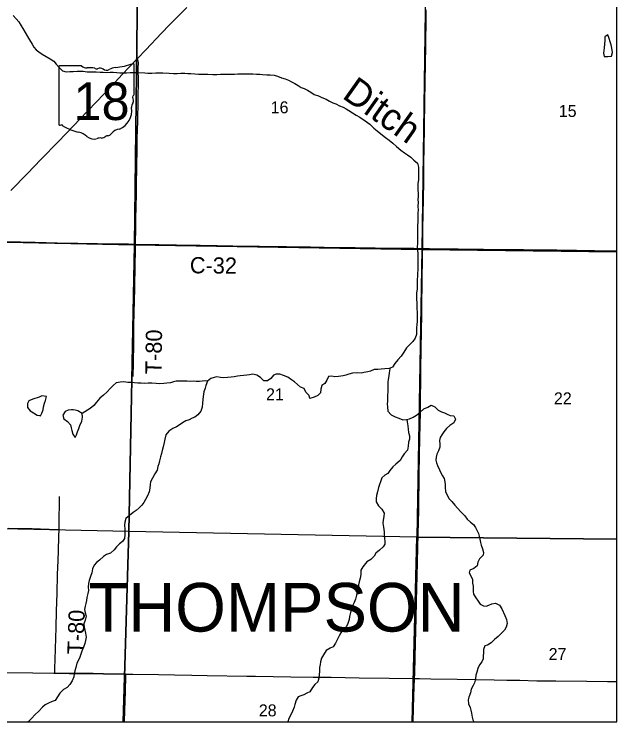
# Model space of a CAD drawing. Extents: x -8.5 to 18.7, y -20.3 to 7.
# Drawn here: x 14.521 to 18.741, y -20.262 to -15.303 of the extents above; entities that cross this region are included whole.
import ezdxf

# ---------------------------------------------------------------- set-up
doc = ezdxf.new("R2010")
doc.units = 0
for name, color, linetype in [('GM_X_Corporation', 7, 'Continuous'), ('GM_X_County_Road', 7, 'Continuous'), ('GM_X_County_Road_Text', 7, 'Continuous'), ('GM_X_Minor_Lake', 7, 'Continuous'), ('GM_X_Minor_River', 7, 'Continuous'), ('GM_X_Minor_River_Text', 7, 'Continuous'), ('GM_X_Section', 7, 'Continuous'), ('GM_X_Section_Text', 7, 'Continuous'), ('GM_X_State_Location', 7, 'Continuous'), ('GM_X_State_Route', 7, 'Continuous'), ('GM_X_State_Shield', 7, 'Continuous'), ('GM_X_Township_Road', 7, 'Continuous'), ('GM_X_Township_Road_Text', 7, 'Continuous'), ('GM_X_Township_Text', 7, 'Continuous'), ('GM_X_Unincorporated_Text', 7, 'Continuous'), ('SH_Cut_Line', 7, 'Continuous')]:
    doc.layers.add(name, color=color, linetype=linetype)

msp = doc.modelspace()

# ---------------------------------------------------------------- linework, layer by layer
at = {"layer": 'GM_X_Corporation'}
msp.add_lwpolyline([(11.2623, -20.262), (18.7413, -20.262), (18.7413, -10.9039)], dxfattribs=at)
at = {"layer": 'GM_X_County_Road'}
for points in [[(14.1487, -16.8895), (14.1591, -16.8897), (14.2125, -16.8915), (14.2784, -16.893), (14.3268, -16.8937), (14.4449, -16.8962), (14.5643, -16.8985), (14.6686, -16.9014), (14.8228, -16.9045), (14.9657, -16.9071), (15.2454, -16.9126), (15.3212, -16.9133), (15.3705, -16.9142)], [(15.3705, -16.9142), (15.5338, -16.9174), (15.6581, -16.9197), (15.8222, -16.9221), (15.9415, -16.9245), (16.0509, -16.9259), (16.2399, -16.9289), (16.3356, -16.9307), (16.3828, -16.9311), (16.4288, -16.9315), (16.4997, -16.9331), (16.5966, -16.934), (16.6924, -16.9355), (16.8079, -16.9372), (16.9099, -16.9383), (17.0491, -16.9399), (17.1635, -16.9417), (17.294, -16.9431), (17.3188, -16.9431), (17.382, -16.9445)], [(17.382, -16.9445), (17.4294, -16.9456), (17.6296, -16.9473), (17.7278, -16.9486), (17.8086, -16.9494), (17.9752, -16.9513), (18.051, -16.9524), (18.087, -16.953), (18.1541, -16.9533), (18.2187, -16.9541), (18.3219, -16.9549), (18.4587, -16.9567), (18.7122, -16.9608), (18.7413, -16.9611)], [(13.3025, -19.8984), (13.3396, -19.8991), (13.4602, -19.9008), (13.5161, -19.9015), (13.5919, -19.9033), (13.8717, -19.9075), (14.0382, -19.9103), (14.124, -19.9116), (14.267, -19.9132), (14.4261, -19.9156), (14.6524, -19.9183), (14.7978, -19.9203), (14.8047, -19.9204)], [(14.8047, -19.9204), (14.906, -19.9221), (14.9744, -19.9227), (15.0738, -19.9242), (15.1472, -19.9246), (15.3033, -19.9272)], [(15.3033, -19.9272), (15.3523, -19.928), (15.5313, -19.931), (15.6432, -19.9329), (15.765, -19.9352), (15.8731, -19.9367), (16.1491, -19.942), (16.2112, -19.9426), (16.4587, -19.9459), (16.6153, -19.9486), (16.7409, -19.9496), (16.9361, -19.9528), (17.1461, -19.9564), (17.3249, -19.9582)], [(17.3249, -19.9582), (17.3585, -19.9585), (17.4395, -19.9602), (17.6222, -19.9634), (17.7552, -19.9655), (17.8833, -19.9681), (17.9715, -19.9697), (18.061, -19.9709), (18.1803, -19.9736), (18.2487, -19.9745), (18.3133, -19.9753), (18.5321, -19.9778), (18.6751, -19.9788), (18.7413, -19.9795)]]:
    msp.add_lwpolyline(points, dxfattribs=at)
at = {"layer": 'GM_X_Minor_Lake'}
for points in [[(18.6631, -15.4571), (18.6579, -15.4602), (18.6563, -15.4875), (18.6547, -15.5133), (18.6523, -15.5383), (18.65, -15.5573), (18.6484, -15.577), (18.6521, -15.6006)], [(18.6521, -15.6006), (18.6771, -15.6007), (18.7036, -15.5978), (18.7105, -15.572), (18.7068, -15.5424), (18.7024, -15.5173), (18.6957, -15.4968), (18.6867, -15.4733), (18.6777, -15.4482), (18.6631, -15.4571)], [(14.7467, -17.9826), (14.7149, -17.9779), (14.696, -17.9862), (14.6504, -18.0011), (14.6224, -18.0124), (14.6132, -18.032), (14.6146, -18.0601), (14.6327, -18.0837), (14.6569, -18.0967), (14.6811, -18.1135), (14.697, -18.1165)], [(14.697, -18.1165), (14.706, -18.1182), (14.7137, -18.0985), (14.7236, -18.075), (14.7252, -18.0553), (14.7337, -18.0296), (14.7406, -18.0091), (14.7467, -17.9826)], [(14.9329, -18.0762), (14.9213, -18.0745), (14.8994, -18.0789), (14.8774, -18.0879), (14.8606, -18.1136), (14.8696, -18.1395), (14.8953, -18.1563), (14.9141, -18.1799), (14.9193, -18.2027), (14.9253, -18.2216), (14.9313, -18.2452), (14.9486, -18.2703)], [(14.9486, -18.2703), (14.9578, -18.2499), (14.9631, -18.2302), (14.9738, -18.2075), (14.9815, -18.1863), (14.9945, -18.156), (14.9999, -18.1279), (14.9962, -18.1021), (14.9675, -18.083), (14.9471, -18.0784), (14.9329, -18.0762)]]:
    msp.add_lwpolyline(points, dxfattribs=at)
at = {"layer": 'GM_X_Minor_River'}
for points in [[(14.5126, -15.3125), (14.5345, -15.3361), (14.5533, -15.3567), (14.5699, -15.3841), (14.5819, -15.4039), (14.5977, -15.4312), (14.6143, -15.4586), (14.6286, -15.4837), (14.6459, -15.5127), (14.6587, -15.5332), (14.6745, -15.5522), (14.6941, -15.566), (14.716, -15.5835), (14.7448, -15.5989), (14.7735, -15.6157), (14.7984, -15.6332), (14.8158, -15.6538), (14.8376, -15.6782), (14.8588, -15.7011), (14.8837, -15.7065), (14.9103, -15.7059), (14.9345, -15.7052)], [(14.9345, -15.7052), (14.961, -15.7023), (14.9822, -15.7024), (15.0034, -15.7033), (15.0322, -15.7064), (15.0527, -15.7065), (15.0754, -15.7081), (15.0958, -15.7082), (15.1239, -15.7091), (15.1443, -15.71), (15.1663, -15.7109), (15.1936, -15.7095), (15.2132, -15.7096), (15.2405, -15.7127), (15.2602, -15.7136), (15.2875, -15.7152), (15.3072, -15.7145), (15.3329, -15.7124), (15.3587, -15.7118), (15.3913, -15.7119), (15.4352, -15.7152), (15.4571, -15.716), (15.4844, -15.7161), (15.5125, -15.7148), (15.5367, -15.7134), (15.5617, -15.7135), (15.6064, -15.716), (15.6359, -15.7184), (15.6624, -15.7185), (15.6874, -15.7171), (15.717, -15.7165), (15.7374, -15.7181), (15.7571, -15.7189), (15.7866, -15.7214), (15.8116, -15.723), (15.8518, -15.7232), (15.876, -15.7241), (15.9109, -15.725), (15.9404, -15.7259), (15.9654, -15.7237), (15.9866, -15.7231), (16.0162, -15.7224), (16.0381, -15.7241), (16.0631, -15.7234), (16.0881, -15.722), (16.1124, -15.7221), (16.1397, -15.7207), (16.1631, -15.7209), (16.1927, -15.7218), (16.2184, -15.7226), (16.2404, -15.7243), (16.2601, -15.7251), (16.2904, -15.7283), (16.3139, -15.7284), (16.3404, -15.7316), (16.3638, -15.7385), (16.3926, -15.7485), (16.4175, -15.7562), (16.441, -15.7654), (16.4674, -15.7792), (16.4871, -15.7891), (16.509, -15.8029), (16.5309, -15.8159), (16.5521, -15.8244), (16.574, -15.8366), (16.5974, -15.8504), (16.6216, -15.8649), (16.6511, -15.8764), (16.6761, -15.8879), (16.7056, -15.8994), (16.7283, -15.9124), (16.7525, -15.9239), (16.7729, -15.9316), (16.8001, -15.9462), (16.8251, -15.9554), (16.8447, -15.9669), (16.8651, -15.9783), (16.89, -15.9944), (16.915, -16.0112), (16.9414, -16.025), (16.9792, -16.0502), (17.0109, -16.0739), (17.0396, -16.1013), (17.0623, -16.1211), (17.0879, -16.1425), (17.1204, -16.1662), (17.1468, -16.186), (17.1733, -16.2074), (17.1989, -16.2303), (17.2276, -16.2562), (17.2533, -16.2745), (17.276, -16.2883), (17.2979, -16.3051), (17.3205, -16.3264), (17.3462, -16.3471), (17.3529, -16.3744), (17.3528, -16.3964), (17.352, -16.4192), (17.3518, -16.4624), (17.3479, -16.4912), (17.3478, -16.5109)], [(17.3478, -16.5109), (17.3485, -16.5367), (17.3499, -16.558), (17.3491, -16.5807), (17.3482, -16.602), (17.3489, -16.6217), (17.3488, -16.649), (17.3495, -16.6756), (17.3486, -16.6953), (17.3484, -16.7552), (17.346, -16.7856), (17.3444, -16.8083), (17.3442, -16.8546), (17.3456, -16.885), (17.3463, -16.907), (17.3431, -16.9365), (17.3453, -16.9578), (17.3475, -16.9828), (17.3481, -17.0056), (17.3479, -17.0557), (17.3486, -17.0747), (17.347, -17.0951), (17.3447, -17.1186), (17.3461, -17.1399), (17.343, -17.1634), (17.3427, -17.2286), (17.3381, -17.2574), (17.338, -17.2832), (17.3386, -17.303), (17.3401, -17.3242), (17.3407, -17.3485), (17.3414, -17.3682), (17.3421, -17.3902), (17.3428, -17.41), (17.3434, -17.432), (17.3433, -17.457), (17.3417, -17.4775), (17.3394, -17.5002), (17.3393, -17.5298), (17.3377, -17.5488), (17.33, -17.5745), (17.3125, -17.5972), (17.2897, -17.6206), (17.2691, -17.6402), (17.2501, -17.6713), (17.231, -17.6992), (17.2074, -17.7257), (17.1869, -17.7499), (17.1693, -17.7771), (17.1473, -17.7861), (17.1155, -17.7882), (17.092, -17.7904), (17.0685, -17.7933), (17.042, -17.7939), (17.0162, -17.8052), (16.9973, -17.8089), (16.9692, -17.8148), (16.9503, -17.8185), (16.9245, -17.8169), (16.8912, -17.8183), (16.8646, -17.8257), (16.8434, -17.8324), (16.8237, -17.8369), (16.7926, -17.8428), (16.7661, -17.8442), (16.7464, -17.8388), (16.7222, -17.841), (16.7092, -17.8682), (16.697, -17.8917), (16.6757, -17.9052), (16.6688, -17.9318), (16.6671, -17.9575), (16.6466, -17.9749), (16.6223, -17.9877), (16.592, -17.9951), (16.5868, -17.9761), (16.5634, -17.951), (16.5506, -17.9251), (16.5257, -17.9159), (16.5038, -17.8976), (16.4841, -17.8801), (16.4637, -17.8648), (16.4381, -17.8457), (16.4078, -17.8357), (16.3813, -17.8249), (16.3556, -17.8248), (16.3366, -17.8331), (16.3191, -17.8565), (16.294, -17.8716), (16.2698, -17.8722), (16.2449, -17.8493), (16.2207, -17.8333), (16.1912, -17.8263), (16.1692, -17.8308), (16.1495, -17.833), (16.1268, -17.8351), (16.104, -17.8365), (16.0851, -17.8402), (16.0608, -17.8447), (16.0411, -17.8469)], [(17.1508, -17.7847), (17.1526, -17.7891), (17.1465, -17.8157), (17.1434, -17.8369), (17.1395, -17.8619), (17.1386, -17.8816), (17.1378, -17.9029), (17.1369, -17.9271), (17.1369, -17.9476), (17.136, -17.9757), (17.1343, -18.0151), (17.1335, -18.0364), (17.1341, -18.0553), (17.1378, -18.0842), (17.162, -18.1101), (17.1884, -18.1254), (17.2141, -18.1346), (17.2429, -18.1446), (17.2694, -18.144), (17.2884, -18.138), (17.3149, -18.1267), (17.3392, -18.1132), (17.3628, -18.0944), (17.3894, -18.0694), (17.4175, -18.0574), (17.4417, -18.0439), (17.4675, -18.0546), (17.4908, -18.0775), (17.5143, -18.089), (17.534, -18.0959), (17.5536, -18.1059), (17.5733, -18.1143), (17.6005, -18.1167), (17.6103, -18.141), (17.5988, -18.166), (17.5722, -18.1849), (17.5479, -18.2067), (17.5304, -18.2294), (17.5167, -18.2498), (17.5052, -18.2695), (17.4998, -18.29), (17.502, -18.3165), (17.5012, -18.3378), (17.4935, -18.362), (17.4798, -18.387), (17.4751, -18.4082), (17.4743, -18.4279), (17.478, -18.4469), (17.4855, -18.4659), (17.4998, -18.4955), (17.5088, -18.5168), (17.5193, -18.5374), (17.5313, -18.5571), (17.5366, -18.5807), (17.5387, -18.6012), (17.5387, -18.6201), (17.5408, -18.6482), (17.5521, -18.6733), (17.5679, -18.6984), (17.5852, -18.7182), (17.6071, -18.7433), (17.6252, -18.7639), (17.6493, -18.7898), (17.6757, -18.8195), (17.6923, -18.8408), (17.7172, -18.8637), (17.7376, -18.879), (17.7504, -18.9003), (17.7639, -18.9231), (17.7714, -18.9429), (17.7774, -18.9619), (17.7819, -18.9816), (17.7871, -19.0044), (17.7916, -19.0241), (17.8005, -19.05), (17.8065, -19.0743), (17.8049, -19.0947), (17.7806, -19.1189), (17.7676, -19.1439), (17.7637, -19.1681), (17.7409, -19.187), (17.7128, -19.1982), (17.7067, -19.2187), (17.7217, -19.243), (17.73, -19.2643), (17.7306, -19.2893), (17.7343, -19.3106), (17.7358, -19.3295), (17.7357, -19.3493), (17.7371, -19.3682), (17.7529, -19.3941), (17.7695, -19.4162), (17.7838, -19.4375), (17.8065, -19.4497), (17.8262, -19.4506), (17.8451, -19.4454), (17.8649, -19.4356), (17.8922, -19.4297), (17.9201, -19.445), (17.9352, -19.4708), (17.9577, -19.5164)], [(16.0411, -17.8469), (15.9896, -17.8504), (15.9661, -17.8495), (15.9411, -17.8449), (15.9222, -17.8493), (15.8987, -17.8553), (15.8736, -17.8757), (15.8636, -17.9044), (15.8582, -17.9249), (15.8498, -17.9506), (15.8451, -17.9817), (15.842, -18.0037), (15.8396, -18.0287), (15.8373, -18.0575), (15.8288, -18.0848), (15.8067, -18.1113), (15.7855, -18.1263), (15.7665, -18.1346), (15.7452, -18.1459), (15.724, -18.1534), (15.699, -18.1669), (15.6769, -18.182), (15.6572, -18.194), (15.6321, -18.2053), (15.6033, -18.2256), (15.5827, -18.2513), (15.5758, -18.2809), (15.5711, -18.3044), (15.5642, -18.3339), (15.558, -18.3612), (15.5534, -18.3816), (15.5457, -18.4059), (15.5381, -18.4332), (15.5327, -18.4536), (15.5273, -18.4733), (15.5211, -18.4983), (15.5066, -18.5248), (15.4891, -18.5543), (15.4746, -18.5808), (15.473, -18.5997), (15.4706, -18.6255), (15.4652, -18.6498), (15.4537, -18.6778), (15.44, -18.7035), (15.4286, -18.7239), (15.4148, -18.7436), (15.3951, -18.7632), (15.3745, -18.7806), (15.354, -18.7949), (15.3274, -18.8168), (15.3023, -18.8379), (15.2947, -18.8636), (15.2938, -18.8841), (15.2952, -18.9114), (15.2967, -18.9319), (15.2958, -18.9509), (15.2935, -18.9767), (15.279, -18.9971), (15.2592, -19.0152), (15.2372, -19.0348), (15.2212, -19.0567), (15.1961, -19.0794), (15.1673, -19.0898), (15.146, -19.1026), (15.1194, -19.1298), (15.0981, -19.1449), (15.0814, -19.1645), (15.0699, -19.1903), (15.0645, -19.2168), (15.0553, -19.2441), (15.0468, -19.2721), (15.0422, -19.2925), (15.0398, -19.3191), (15.042, -19.3426), (15.0358, -19.3638), (15.0297, -19.3918), (15.0266, -19.4123), (15.0227, -19.432), (15.0181, -19.4517), (15.0134, -19.4744), (15.0179, -19.4972), (15.0238, -19.5223), (15.0184, -19.5496), (15.0092, -19.5753), (15.0107, -19.5996), (15.0166, -19.6193), (15.0211, -19.6398), (15.0255, -19.6694), (15.0209, -19.6914), (15.0155, -19.7126), (15.0055, -19.7391), (14.9941, -19.7656), (14.9872, -19.7868), (14.9795, -19.808), (14.9711, -19.8308), (14.9596, -19.8519), (14.9519, -19.8815), (14.9465, -19.905), (14.9419, -19.9254), (14.938, -19.9459), (14.9266, -19.9739)], [(15.8736, -17.8757), (15.8577, -17.8733), (15.8372, -17.8755), (15.8175, -17.8761), (15.7963, -17.8776), (15.7743, -17.8759), (15.7547, -17.8766), (15.7319, -17.8757), (15.7069, -17.8756), (15.6819, -17.874), (15.6562, -17.8739), (15.6357, -17.8791), (15.6152, -17.8858), (15.5902, -17.8887), (15.5682, -17.8901), (15.5402, -17.8923), (15.5152, -17.8906), (15.4857, -17.889), (15.4599, -17.8896), (15.4319, -17.8903), (15.4099, -17.8894), (15.3857, -17.8878), (15.3637, -17.8854), (15.344, -17.8838), (15.3168, -17.8836), (15.2895, -17.8805), (15.2622, -17.8819), (15.2357, -17.8855), (15.2137, -17.9044), (15.1939, -17.9263), (15.1711, -17.9505), (15.1467, -17.9724), (15.1217, -17.9942), (15.0965, -18.0222), (15.0775, -18.0464), (15.0532, -18.0667), (14.9962, -18.1021)], [(17.2695, -18.1439), (17.2731, -18.1599), (17.2768, -18.188), (17.2797, -18.21), (17.2819, -18.2343), (17.2894, -18.2571), (17.2885, -18.2814), (17.2831, -18.3026), (17.2808, -18.3307), (17.2754, -18.3572), (17.251, -18.3829), (17.2388, -18.4056), (17.2228, -18.4298), (17.1947, -18.4562), (17.1734, -18.4743), (17.1513, -18.5007), (17.1376, -18.5227), (17.1156, -18.5332), (17.0958, -18.5528), (17.0866, -18.5793), (17.0797, -18.599), (17.072, -18.6202), (17.0651, -18.6498), (17.0589, -18.6748), (17.0551, -18.696), (17.055, -18.721), (17.073, -18.7476), (17.0957, -18.7713), (17.113, -18.7987), (17.1098, -18.8237), (17.1052, -18.8487), (17.1028, -18.8707), (17.1065, -18.8972), (17.1109, -18.9299), (17.1116, -18.9504), (17.1145, -18.9762), (17.1167, -18.9951), (17.1159, -19.0164), (17.106, -19.0368), (17.0801, -19.0579), (17.0535, -19.0806), (17.0413, -19.101), (17.0192, -19.1244), (16.9904, -19.1417), (16.9615, -19.1749), (16.9492, -19.1992), (16.9476, -19.2302), (16.9437, -19.2553), (16.936, -19.2818), (16.9314, -19.303), (16.929, -19.3288), (16.9259, -19.3485), (16.9182, -19.3742), (16.9105, -19.4023), (16.9014, -19.425), (16.8907, -19.4499), (16.8799, -19.4772), (16.873, -19.5045), (16.8699, -19.5234), (16.8668, -19.5454), (16.8583, -19.5719), (16.8484, -19.5946), (16.8256, -19.6158), (16.8081, -19.6392), (16.7966, -19.6589), (16.7852, -19.6823), (16.7714, -19.7103), (16.7539, -19.7353), (16.7334, -19.7465), (16.7068, -19.7631), (16.6878, -19.7918), (16.6725, -19.8153), (16.6656, -19.841), (16.6625, -19.86), (16.6594, -19.8812), (16.6585, -19.9093), (16.6561, -19.9305), (16.6545, -19.9548), (16.6476, -19.9805), (16.6263, -20.0009), (16.6088, -20.022), (16.5905, -20.0515), (16.5708, -20.0605), (16.5495, -20.0733), (16.5283, -20.0801), (16.5093, -20.0876), (16.4948, -20.111), (16.4871, -20.1398), (16.481, -20.1602), (16.4702, -20.1867), (16.458, -20.2132), (16.4435, -20.2382), (16.4366, -20.262)], [(17.9577, -19.5164), (17.969, -19.5453), (17.9742, -19.5719), (17.9657, -19.5984), (17.9543, -19.6188), (17.9345, -19.6407), (17.9094, -19.6634), (17.8835, -19.6852), (17.8615, -19.7086), (17.8364, -19.7244), (17.8167, -19.7297), (17.8067, -19.7554), (17.8067, -19.7766), (17.8058, -19.8017), (17.8042, -19.8206), (17.7958, -19.8418), (17.7806, -19.8615), (17.7668, -19.8879), (17.7599, -19.9145), (17.7537, -19.9357), (17.7506, -19.9607), (17.7444, -19.988), (17.7353, -20.0076), (17.7215, -20.0341), (17.7169, -20.0591), (17.7054, -20.0887), (17.6992, -20.1083), (17.7022, -20.1349), (17.7134, -20.1607), (17.7186, -20.1812), (17.7246, -20.2002), (17.729, -20.2283), (17.7327, -20.2488), (17.7408, -20.262)], [(14.9266, -19.9739), (14.9113, -20.0004), (14.8923, -20.0215), (14.8665, -20.0351), (14.8414, -20.0607), (14.8231, -20.0864), (14.8071, -20.1121), (14.7874, -20.1204), (14.76, -20.1301), (14.7388, -20.1429), (14.719, -20.1595), (14.6939, -20.1867), (14.6681, -20.2109), (14.6429, -20.2388), (14.6209, -20.2592), (14.6175, -20.262)]]:
    msp.add_lwpolyline(points, dxfattribs=at)
at = {"layer": 'GM_X_Section'}
for points in [[(13.3845, -14.866), (15.3877, -14.9113), (15.3636, -16.9183), (13.3536, -16.8784)], [(15.3877, -14.9113), (17.403, -14.9422), (17.3759, -16.9531), (15.3636, -16.9183)], [(13.3536, -16.8784), (15.3636, -16.9183), (15.3229, -18.9276), (13.322, -18.8853)], [(15.3636, -16.9183), (17.3759, -16.9531), (17.3412, -18.9669), (15.3229, -18.9276)]]:
    msp.add_lwpolyline(points, close=True, dxfattribs=at)
at = {"layer": 'GM_X_State_Route'}
msp.add_lwpolyline([(14.4984, -16.5388), (14.6137, -16.4204), (14.7084, -16.3216), (14.8304, -16.1957), (14.9844, -16.0351), (15.0287, -15.988), (15.1031, -15.9112), (15.1739, -15.8361), (15.2273, -15.7788), (15.2771, -15.7266), (15.3255, -15.6749), (15.3818, -15.6152), (15.3838, -15.6131), (15.4421, -15.5521), (15.5519, -15.4364), (15.6089, -15.3774), (15.6454, -15.3394), (15.7291, -15.2557)], dxfattribs=at)
at = {"layer": 'GM_X_State_Shield'}
for p, q in [((14.9929, -15.666), (14.8385, -15.666)), ((15.3606, -15.8654), (15.3606, -15.6561)), ((14.8333, -15.6729), (14.8333, -16.0731)), ((15.3606, -15.8654), (15.3606, -15.8654))]:
    msp.add_line(p, q, dxfattribs=at)
for centre, radius, start, end in [((14.8393, -15.672), 0.00611, 98.1301, 188.1301), ((15.0297, -15.6195), 0.0593, 231.6195, 271.1119), ((15.1728, -15.1203), 0.5592, 275.8445, 288.9065), ((15.3548, -15.6552), 0.00587, 351.8621, 97.738), ((15.0494, -15.8907), 0.2127, 80.4867, 94.9883), ((15.0976, -15.6699), 0.0171, 219.7921, 297.1024), ((15.1227, -15.7162), 0.0355, 54.4667, 119.1411), ((15.1686, -15.6527), 0.0428, 233.8562, 294.8282), ((15.2441, -15.7882), 0.1125, 97.3462, 120.7689), ((15.3544, -15.8662), 0.00628, 289.6038, 7.7341), ((15.3593, -15.8808), 0.00909, 107.944, 210.337), ((15.3015, -15.9073), 0.0545, 340.033, 23.6496), ((15.2041, -15.9797), 0.1399, 292.3089, 8.9858), ((15.3817, -15.953), 0.0397, 136.8065, 186.9296), ((14.8394, -16.074), 0.00616, 171.9584, 258.3066), ((14.8403, -16.033), 0.047, 267.339, 280.6039), ((14.85, -16.0962), 0.017, 29.7484, 93.2717), ((15.0641, -15.7366), 0.4038, 240.4129, 257.1985), ((15.2631, -16.1855), 0.0766, 94.4031, 142.5768), ((14.9437, -16.2529), 0.1264, 47.1842, 75.836), ((15.0803, -16.0982), 0.0802, 230.7004, 286.2918), ((15.1325, -16.1281), 0.0427, 268.777, 315.5493), ((15.1712, -16.1669), 0.012, 65.7517, 132.6484), ((15.166, -16.1119), 0.0452, 282.8732, 323.2771), ((15.1267, -16.2366), 0.0659, 85.6951, 111.2099)]:
    msp.add_arc(centre, radius, start, end, dxfattribs=at)
at = {"layer": 'GM_X_Township_Road'}
for points in [[(17.382, -16.9445), (17.3821, -16.9403), (17.382, -16.903), (17.3831, -16.8508), (17.3837, -16.7812), (17.3846, -16.729), (17.3849, -16.7004), (17.3863, -16.6022), (17.3886, -16.4754), (17.3897, -16.3884), (17.3904, -16.3163), (17.391, -16.2703), (17.3915, -16.2368), (17.392, -16.207), (17.3933, -16.1312), (17.3948, -16.0516), (17.3958, -15.9563), (17.3971, -15.9075), (17.3988, -15.7863), (17.3995, -15.7261), (17.4002, -15.6992), (17.4013, -15.6652), (17.4021, -15.613), (17.403, -15.5646), (17.4032, -15.5078), (17.4039, -15.4597), (17.4049, -15.3898), (17.4068, -15.2734)], [(15.3705, -16.9142), (15.3706, -16.9042), (15.372, -16.8084), (15.3732, -16.7376), (15.3766, -16.5648), (15.3779, -16.494), (15.3799, -16.3759), (15.3821, -16.2454), (15.3832, -16.1708), (15.3857, -16.054), (15.3884, -15.9061), (15.3903, -15.7557), (15.3895, -15.7021), (15.39, -15.678), (15.3905, -15.6442), (15.3898, -15.6311), (15.3875, -15.6242), (15.3838, -15.6131)], [(15.354, -17.8426), (15.3553, -17.7481), (15.358, -17.6077), (15.3597, -17.4821), (15.3646, -17.2261), (15.3682, -17.0545), (15.3695, -16.9663), (15.3704, -16.9253), (15.3705, -16.9142)], [(17.3249, -19.9582), (17.3259, -19.9248), (17.3288, -19.8079), (17.3337, -19.6215), (17.3364, -19.5345), (17.3391, -19.4153), (17.3416, -19.3284), (17.346, -19.1448), (17.3482, -19.035), (17.353, -18.8609), (17.3541, -18.7863), (17.3548, -18.6958), (17.3568, -18.5914), (17.3577, -18.5223), (17.3619, -18.2726), (17.3656, -18.0914), (17.3672, -17.9808), (17.3685, -17.8875), (17.3695, -17.7858), (17.3729, -17.5196), (17.3747, -17.4126), (17.3758, -17.3244), (17.3773, -17.1988), (17.381, -16.9788), (17.382, -16.9445)], [(14.8371, -18.71), (14.8372, -18.7), (14.8373, -18.683)], [(14.8347, -18.9133), (14.8351, -18.893), (14.8351, -18.8805), (14.8351, -18.8594), (14.8371, -18.71)], [(14.4775, -18.9059), (14.5471, -18.9071), (14.5956, -18.9079), (14.6465, -18.9083), (14.7659, -18.912), (14.8243, -18.9131), (14.8347, -18.9133)], [(14.8047, -19.9204), (14.8049, -19.9099), (14.8054, -19.885), (14.8072, -19.8242), (14.8141, -19.6016), (14.8173, -19.4872), (14.8215, -19.3592), (14.825, -19.2286), (14.8281, -19.1317), (14.8302, -19.0646), (14.8335, -18.9626), (14.8347, -18.9133)], [(15.3033, -19.9272), (15.1472, -19.9246), (15.0738, -19.9242), (14.9744, -19.9227), (14.906, -19.9221), (14.8047, -19.9204)], [(15.2941, -20.262), (15.2964, -20.1817), (15.3007, -20.0524), (15.3031, -19.9381), (15.3033, -19.9272)], [(17.3157, -20.262), (17.3158, -20.2566), (17.3207, -20.0819), (17.3249, -19.9582)]]:
    msp.add_lwpolyline(points, dxfattribs=at)
at = {"layer": 'GM_X_Unincorporated_Text'}
for points in [[(18.7413, -16.9689), (18.7413, -14.9582), (17.403, -14.9422), (17.3759, -16.9531)], [(18.7413, -18.9815), (18.7413, -16.9689), (17.3759, -16.9531), (17.3412, -18.9669)], [(13.2833, -20.262), (15.2847, -20.262), (15.3229, -18.9276), (13.322, -18.8853)], [(15.2847, -20.262), (17.3084, -20.262), (17.3412, -18.9669), (15.3229, -18.9276)], [(17.3084, -20.262), (18.7413, -20.262), (18.7413, -18.9815), (17.3412, -18.9669)]]:
    msp.add_lwpolyline(points, close=True, dxfattribs=at)
at = {"layer": 'SH_Cut_Line'}
msp.add_lwpolyline([(-8.4587, -10.6981), (-8.4587, -20.262), (18.7413, -20.262), (18.7413, -10.9039)], dxfattribs=at)

# ---------------------------------------------------------------- texts
at = {"layer": 'GM_X_County_Road_Text'}
msp.add_text('C-32', height=0.11364, rotation=359.3163, dxfattribs=at).set_placement((15.7507, -17.1185))
at = {"layer": 'GM_X_Minor_River_Text'}
msp.add_text('Ditch', height=0.18949, rotation=324.7724, dxfattribs=at).set_placement((16.8098, -15.8859))
at = {"layer": 'GM_X_Section_Text'}
for s, p in [('16', (16.3173, -15.9976)), ('15', (18.3348, -16.0232)), ('21', (16.2848, -18.0086)), ('22', (18.3006, -18.037)), ('27', (18.264, -19.8284)), ('28', (16.234, -20.2234))]:
    msp.add_text(s, height=0.08371, rotation=0, dxfattribs=at).set_placement(p)
at = {"layer": 'GM_X_State_Location'}
for s in ['s', 'r']:
    msp.add_text(s, height=0.000379, dxfattribs=at).set_placement((15.091, -15.8996))
msp.add_text('18', height=0.000379, rotation=0, dxfattribs=at).set_placement((14.9956, -15.9271))
at = {"layer": 'GM_X_State_Shield'}
msp.add_text('18', height=0.26367, dxfattribs=at).set_placement((14.9367, -16.0449))
at = {"layer": 'GM_X_Township_Road_Text'}
for rotation, p in [(89.2976, (15.5529, -17.826)), (88.2318, (15.0061, -19.7905))]:
    msp.add_text('T-80', height=0.11364, rotation=rotation, dxfattribs=at).set_placement(p)
at = {"layer": 'GM_X_Township_Text'}
msp.add_text('THOMPSON', height=0.34091, rotation=0, dxfattribs=at).set_placement((15.0409, -19.6294))

doc.saveas('drawing.dxf')
